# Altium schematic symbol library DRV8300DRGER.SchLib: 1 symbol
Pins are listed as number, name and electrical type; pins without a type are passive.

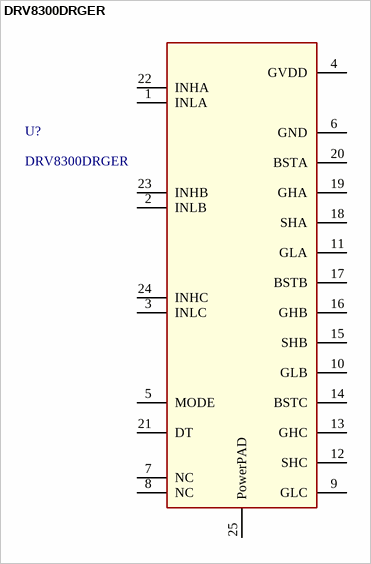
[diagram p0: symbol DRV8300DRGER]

## DRV8300DRGER
designator U?
100-V max simple 3-phase gate driver with bootstrap diodes 24-VQFN -40 to 125; Manufacturer_Name: Texas Instruments
footprint RGE0024B-IPC_A
pins: 1 INLA, 2 INLB, 3 INLC, 4 GVDD, 5 MODE, 6 GND, 7 NC, 8 NC, 9 GLC, 10 GLB, 11 GLA, 12 SHC, 13 GHC, 14 BSTC, 15 SHB, 16 GHB, 17 BSTB, 18 SHA, 19 GHA, 20 BSTA, 21 DT, 22 INHA, 23 INHB, 24 INHC, 25 PowerPAD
